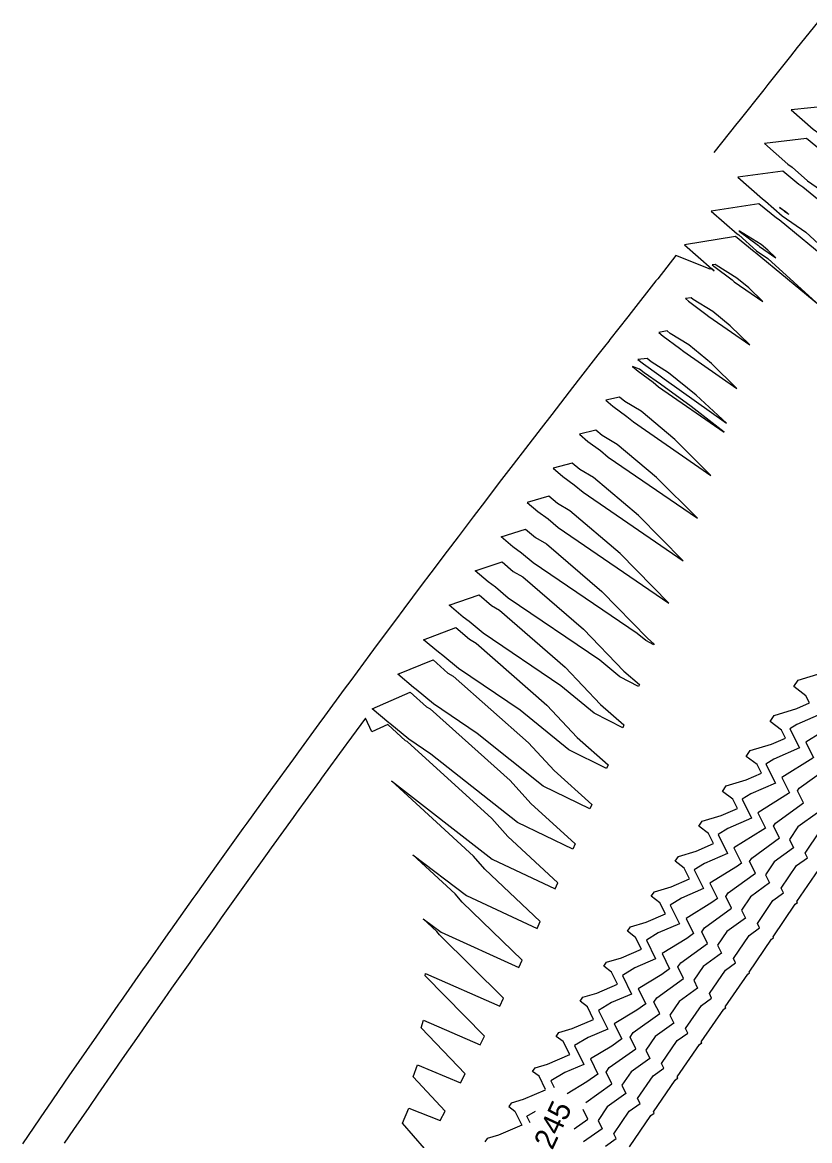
# Model space of a CAD drawing. Extents: x 1160447 to 1162032, y 616022 to 618272.
# Drawn here: x 1160785.4 to 1160877.4, y 616560 to 616690.7 of the extents above; entities that cross this region are included whole.
import ezdxf

# ---------------------------------------------------------------- set-up
doc = ezdxf.new("R2010")
doc.units = 0
doc.layers.add('D_Contours_Major', color=7, linetype='Continuous')
doc.layers.add('D_Contours_Minor', color=7, linetype='Continuous')

msp = doc.modelspace()

# ---------------------------------------------------------------- linework, layer by layer
at = {"layer": 'D_Contours_Major'}
for points in [[(1160880.5, 616608.73), (1160876.97, 616606.53), (1160877.88, 616604.7)], [(1160877.82, 616604.68), (1160874.17, 616602.41), (1160875.07, 616600.6), (1160874.97, 616600.52), (1160871.37, 616598.29), (1160872.27, 616596.49), (1160871.97, 616596.28), (1160868.58, 616594.17), (1160869.46, 616592.38), (1160868.99, 616592.04), (1160865.78, 616590.05), (1160866.66, 616588.28), (1160866.02, 616587.81), (1160862.99, 616585.92), (1160863.86, 616584.17), (1160863.07, 616583.59), (1160860.19, 616581.82), (1160861.06, 616580.06), (1160860.14, 616579.39), (1160857.4, 616577.72), (1160858.27, 616575.95), (1160857.22, 616575.2), (1160854.6, 616573.62), (1160855.47, 616571.84), (1160854.31, 616571.02), (1160851.81, 616569.51), (1160852.67, 616567.73), (1160851.41, 616566.83), (1160849.1, 616565.43)]]:
    msp.add_lwpolyline(points, dxfattribs=at)
at = {"layer": 'D_Contours_Minor'}
for points in [[(1160878.35, 616690.68), (1160875.99, 616687.73), (1160875.2, 616686.75), (1160872.55, 616683.42), (1160872.06, 616682.81), (1160869.14, 616679.14), (1160868.93, 616678.87), (1160866.22, 616675.46)], [(1160878.81, 616675.68), (1160877.06, 616677.1), (1160872.16, 616676.52), (1160874.89, 616674.12), (1160875.39, 616673.75), (1160877.18, 616672.17), (1160881.33, 616669.26)], [(1160888, 616662.09), (1160876.65, 616671.43), (1160876.16, 616671.74), (1160874.28, 616673.28), (1160869.04, 616672.57), (1160871.93, 616670.04), (1160872.26, 616669.79), (1160874.21, 616668.08), (1160876.98, 616666.14), (1160886.33, 616657.54)], [(1160885.94, 616657.63), (1160873.86, 616667.6), (1160873.54, 616667.8), (1160871.51, 616669.47), (1160865.91, 616668.63), (1160868.97, 616665.96), (1160869.14, 616665.83), (1160871.24, 616663.99), (1160872.53, 616663.09), (1160878.61, 616657.53), (1160871.08, 616663.77), (1160870.94, 616663.86), (1160868.75, 616665.66), (1160862.79, 616664.68), (1160866.01, 616661.88), (1160866.01, 616661.87), (1160866.27, 616661.65), (1160866, 616661.87), (1160865.81, 616661.83), (1160861.81, 616663.43), (1160859.68, 616660.72), (1160859.46, 616660.45), (1160856.57, 616656.77), (1160856.17, 616656.25), (1160854.09, 616653.6), (1160853.95, 616653.42), (1160853.47, 616652.81), (1160852.69, 616651.8), (1160850.37, 616648.84), (1160849.35, 616647.51), (1160847.29, 616644.86), (1160846.05, 616643.25), (1160844.22, 616640.87), (1160842.78, 616639), (1160841.16, 616636.88), (1160839.55, 616634.76), (1160838.11, 616632.87), (1160836.35, 616630.54), (1160835.07, 616628.86), (1160833.17, 616626.34), (1160832.05, 616624.84), (1160830.03, 616622.14), (1160829.04, 616620.81), (1160826.91, 616617.95), (1160826.04, 616616.77), (1160823.81, 616613.76), (1160823.05, 616612.72), (1160820.74, 616609.58), (1160820.07, 616608.67), (1160817.69, 616605.41), (1160817.1, 616604.6), (1160814.67, 616601.24), (1160814.15, 616600.53), (1160811.66, 616597.07), (1160811.21, 616596.45), (1160808.67, 616592.91), (1160808.28, 616592.36), (1160805.71, 616588.74), (1160805.36, 616588.26), (1160802.76, 616584.58), (1160802.45, 616584.15), (1160799.83, 616580.41), (1160799.56, 616580.03), (1160796.91, 616576.24), (1160796.68, 616575.91), (1160794.02, 616572.07), (1160793.81, 616571.78), (1160791.14, 616567.91), (1160790.95, 616567.63), (1160788.28, 616563.74), (1160788.11, 616563.48), (1160785.44, 616559.57)], [(1160846.57, 616565.93), (1160845.82, 616567.48), (1160845.05, 616568.05), (1160845.34, 616568.47), (1160846.81, 616568.9), (1160849.39, 616570.01), (1160848.64, 616571.55), (1160847.83, 616572.15), (1160848.13, 616572.6), (1160849.68, 616573.05), (1160852.18, 616574.12), (1160851.46, 616575.61), (1160850.6, 616576.25), (1160850.92, 616576.71), (1160852.56, 616577.2), (1160854.98, 616578.24), (1160854.28, 616579.67), (1160853.38, 616580.34), (1160853.71, 616580.82), (1160855.44, 616581.34), (1160857.78, 616582.35), (1160857.1, 616583.72), (1160856.16, 616584.43), (1160856.5, 616584.94), (1160858.34, 616585.48), (1160860.58, 616586.46), (1160859.93, 616587.77), (1160858.93, 616588.52), (1160859.29, 616589.05), (1160861.24, 616589.64), (1160863.39, 616590.57), (1160862.77, 616591.82), (1160861.71, 616592.61), (1160862.09, 616593.18), (1160864.16, 616593.8), (1160866.19, 616594.68), (1160865.61, 616595.86), (1160864.48, 616596.7), (1160864.89, 616597.3), (1160867.09, 616597.96), (1160869, 616598.79), (1160868.45, 616599.89), (1160867.26, 616600.79), (1160867.69, 616601.42), (1160870.03, 616602.13), (1160871.81, 616602.9), (1160871.3, 616603.93), (1160870.03, 616604.88), (1160870.48, 616605.55), (1160872.98, 616606.3), (1160874.61, 616607.01), (1160874.15, 616607.95), (1160872.81, 616608.97), (1160873.28, 616609.67), (1160875.93, 616610.47), (1160877.42, 616611.12), (1160877, 616611.97), (1160875.58, 616613.05), (1160876.09, 616613.8), (1160878.9, 616614.64)], [(1160832.43, 616559.04), (1160829.86, 616562), (1160830.6, 616563.74), (1160834.24, 616562.3), (1160834.83, 616563.39), (1160831.11, 616567.42), (1160831.62, 616568.8), (1160836.62, 616566.72), (1160837.17, 616567.76), (1160832.02, 616573.13), (1160832.3, 616574.04), (1160838.94, 616571.17), (1160839.45, 616572.17), (1160832.49, 616579.22), (1160832.55, 616579.51), (1160841.21, 616575.67), (1160841.67, 616576.61), (1160834.17, 616584.02), (1160833.85, 616584.39), (1160832.26, 616585.9), (1160834.37, 616584.32), (1160843.43, 616580.2), (1160843.84, 616581.07), (1160836.82, 616587.84), (1160835.99, 616588.8), (1160831.08, 616593.38), (1160837.35, 616588.6), (1160845.59, 616584.77), (1160845.95, 616585.57), (1160839.49, 616591.68), (1160838.14, 616593.21), (1160828.57, 616602), (1160840.32, 616592.88), (1160847.7, 616589.39), (1160848.01, 616590.1), (1160842.17, 616595.52), (1160840.28, 616597.62), (1160830.39, 616606.6), (1160830.2, 616606.7), (1160828.13, 616608.6), (1160826.29, 616607.75), (1160825.53, 616609.34), (1160823.35, 616606.38), (1160823.24, 616606.23), (1160820.39, 616602.32), (1160820.15, 616601.98), (1160817.44, 616598.25), (1160817.07, 616597.75), (1160814.5, 616594.17), (1160814.03, 616593.51), (1160811.57, 616590.08), (1160811, 616589.28), (1160808.65, 616585.99), (1160807.99, 616585.04), (1160805.75, 616581.88), (1160804.99, 616580.79), (1160802.86, 616577.77), (1160802, 616576.54), (1160799.98, 616573.65), (1160799.04, 616572.29), (1160797.11, 616569.52), (1160796.1, 616568.05), (1160794.26, 616565.38), (1160793.2, 616563.84), (1160791.42, 616561.24), (1160790.33, 616559.65)], [(1160879.05, 616609.96), (1160875.93, 616608.6), (1160875.13, 616608.1), (1160876.25, 616605.86), (1160873.25, 616604.55), (1160872.33, 616603.98), (1160873.44, 616601.75), (1160870.55, 616600.49), (1160869.53, 616599.86), (1160870.63, 616597.64), (1160867.86, 616596.43), (1160866.73, 616595.73), (1160867.83, 616593.53), (1160865.16, 616592.37), (1160863.94, 616591.61), (1160865.03, 616589.43), (1160862.45, 616588.3), (1160861.14, 616587.49), (1160862.22, 616585.32), (1160859.74, 616584.24), (1160858.35, 616583.38), (1160859.42, 616581.21), (1160857.02, 616580.17), (1160855.55, 616579.27), (1160856.62, 616577.09), (1160854.29, 616576.09), (1160852.76, 616575.16), (1160853.83, 616572.98), (1160851.57, 616572.02), (1160849.97, 616571.06), (1160851.03, 616568.87), (1160848.84, 616567.93), (1160847.18, 616566.93), (1160847.56, 616566.15)], [(1160851.27, 616564.42), (1160854.32, 616566.59), (1160853.65, 616567.97), (1160854.01, 616568.5), (1160857.11, 616570.7), (1160856.44, 616572.07), (1160856.8, 616572.59), (1160859.91, 616574.81), (1160859.24, 616576.16), (1160859.59, 616576.67), (1160862.7, 616578.92), (1160862.04, 616580.26), (1160862.38, 616580.75), (1160865.5, 616583.02), (1160864.83, 616584.36), (1160865.15, 616584.83), (1160868.3, 616587.13), (1160867.63, 616588.48), (1160867.92, 616588.91), (1160871.1, 616591.23), (1160870.42, 616592.6), (1160870.69, 616592.99), (1160873.9, 616595.34), (1160873.21, 616596.72), (1160873.45, 616597.07), (1160876.71, 616599.44), (1160876.01, 616600.83), (1160876.22, 616601.15), (1160879.51, 616603.54)], [(1160878.34, 616598.29), (1160876.06, 616596.63), (1160875.06, 616595.15), (1160875.54, 616594.19), (1160873.29, 616592.55), (1160872.26, 616591.03), (1160872.74, 616590.08), (1160870.53, 616588.47), (1160869.47, 616586.91), (1160869.94, 616585.98), (1160867.76, 616584.39), (1160866.68, 616582.8), (1160867.14, 616581.88), (1160864.99, 616580.31), (1160863.88, 616578.7), (1160864.34, 616577.77), (1160862.19, 616576.22), (1160861.08, 616574.61), (1160861.55, 616573.67), (1160859.38, 616572.12), (1160858.29, 616570.52), (1160858.76, 616569.56), (1160856.58, 616568.01), (1160855.49, 616566.43), (1160855.96, 616565.45), (1160853.78, 616563.9), (1160852.71, 616562.3), (1160853.17, 616561.34), (1160851.02, 616559.81)], [(1160853.58, 616559.32), (1160854.82, 616560.21), (1160854.55, 616560.76), (1160856.33, 616563.4), (1160857.61, 616564.31), (1160857.33, 616564.89), (1160859.14, 616567.53), (1160860.4, 616568.42), (1160860.13, 616568.97), (1160861.97, 616571.65), (1160863.19, 616572.52), (1160862.93, 616573.06), (1160864.79, 616575.77), (1160865.98, 616576.63), (1160865.73, 616577.14), (1160867.6, 616579.87), (1160868.78, 616580.73), (1160868.53, 616581.23), (1160870.37, 616583.95), (1160871.58, 616584.83), (1160871.32, 616585.35), (1160873.13, 616588.03), (1160874.37, 616588.93), (1160874.11, 616589.46), (1160875.9, 616592.11), (1160877.17, 616593.03), (1160876.9, 616593.58), (1160878.67, 616596.18)], [(1160856.39, 616559.22), (1160858.88, 616562.91), (1160859.25, 616563.18), (1160859.17, 616563.34), (1160861.71, 616567.04), (1160862.04, 616567.28), (1160861.97, 616567.42), (1160864.55, 616571.18), (1160864.83, 616571.38), (1160864.77, 616571.5), (1160867.39, 616575.31), (1160867.62, 616575.48), (1160867.57, 616575.58), (1160870.21, 616579.43), (1160870.42, 616579.58), (1160870.37, 616579.67), (1160872.98, 616583.51), (1160873.21, 616583.68), (1160873.16, 616583.78), (1160875.74, 616587.59), (1160876.01, 616587.78), (1160875.95, 616587.9), (1160878.51, 616591.66)], [(1160846.54, 616565.87), (1160843.94, 616564.76), (1160842.54, 616564.34), (1160842.27, 616563.94), (1160843, 616563.4), (1160843.8, 616561.77), (1160841.09, 616560.61), (1160839.75, 616560.21), (1160839.49, 616559.83)], [(1160844.76, 616562.04), (1160844.39, 616562.8), (1160845.4, 616563.41)], [(1160849.92, 616561.33), (1160851.53, 616562.48), (1160850.98, 616563.6)]]:
    msp.add_lwpolyline(points, dxfattribs=at)
for points in [[(1160881.47, 616679.63), (1160879.86, 616680.93), (1160875.29, 616680.45), (1160877.86, 616678.19), (1160878.51, 616677.72), (1160880.16, 616676.26), (1160885.57, 616672.44), (1160892.49, 616666), (1160905, 616658.76), (1160905.4, 616660.07), (1160894.52, 616668.78), (1160892.21, 616670.99), (1160882.26, 616679.12)], [(1160874.55, 616668.55), (1160874.52, 616668.58), (1160873.89, 616669.05), (1160874.59, 616668.61), (1160874.78, 616668.46), (1160875, 616668.24)], [(1160869.22, 616666.27), (1160869.2, 616666.29), (1160869.15, 616666.28), (1160869.18, 616666.26), (1160871.45, 616664.59), (1160871.59, 616664.47), (1160873.47, 616663.15), (1160872.54, 616664.06), (1160871.76, 616664.7)], [(1160866.51, 616662.29), (1160866.38, 616662.39), (1160866.04, 616662.34), (1160866.22, 616662.17), (1160868.38, 616660.59), (1160868.63, 616660.37), (1160871.95, 616658.06), (1160870.32, 616659.64), (1160868.93, 616660.79)], [(1160863.81, 616658.3), (1160863.57, 616658.5), (1160862.93, 616658.39), (1160863.27, 616658.08), (1160865.31, 616656.59), (1160865.67, 616656.28), (1160870.44, 616652.97), (1160868.13, 616655.22), (1160866.11, 616656.9)], [(1160861.14, 616654.32), (1160860.78, 616654.62), (1160859.82, 616654.43), (1160860.33, 616654), (1160862.24, 616652.61), (1160862.73, 616652.2), (1160868.93, 616647.88), (1160865.96, 616650.79), (1160863.31, 616653)], [(1160858.92, 616651), (1160858.45, 616651.38), (1160857.34, 616651.27), (1160858.01, 616650.77), (1160859.82, 616649.46), (1160860.43, 616649), (1160867.73, 616643.81), (1160864.18, 616647.1), (1160860.95, 616649.73)], [(1160858.08, 616649.73), (1160857.55, 616650.13), (1160856.72, 616650.47), (1160857.38, 616649.9), (1160859.16, 616648.61), (1160859.77, 616648.08), (1160867.43, 616642.79), (1160863.57, 616645.76), (1160860, 616648.4)], [(1160855.83, 616646.37), (1160855.22, 616646.88), (1160853.63, 616646.51), (1160854.45, 616645.8), (1160856.08, 616644.62), (1160856.83, 616643.97), (1160865.9, 616637.73), (1160861.68, 616641.91), (1160857.73, 616645.23)], [(1160853.2, 616642.39), (1160852.46, 616643.01), (1160850.55, 616642.54), (1160851.52, 616641.7), (1160853, 616640.62), (1160853.89, 616639.86), (1160864.31, 616632.71), (1160859.55, 616637.47), (1160854.95, 616641.35)], [(1160850.58, 616638.41), (1160849.7, 616639.16), (1160847.48, 616638.55), (1160848.59, 616637.6), (1160849.93, 616636.63), (1160850.96, 616635.75), (1160862.67, 616627.73), (1160857.42, 616633.03), (1160852.18, 616637.47)], [(1160847.97, 616634.44), (1160846.96, 616635.3), (1160844.42, 616634.56), (1160845.67, 616633.49), (1160846.86, 616632.64), (1160848.03, 616631.63), (1160860.99, 616622.8), (1160855.28, 616628.6), (1160849.42, 616633.59)], [(1160844.23, 616631.45), (1160845.38, 616630.47), (1160846.67, 616629.72), (1160853.14, 616624.16), (1160858.47, 616618.7), (1160859.28, 616618), (1160859.24, 616617.9), (1160858.27, 616618.41), (1160857.29, 616619.23), (1160845.11, 616627.51), (1160843.78, 616628.65), (1160842.76, 616629.38), (1160841.37, 616630.56)], [(1160841.51, 616627.61), (1160842.8, 616626.49), (1160843.93, 616625.85), (1160851, 616619.73), (1160855.73, 616614.83), (1160857.53, 616613.27), (1160857.45, 616613.05), (1160855.27, 616614.16), (1160852.9, 616616.13), (1160842.2, 616623.39), (1160840.71, 616624.65), (1160839.85, 616625.27), (1160838.34, 616626.55)], [(1160838.8, 616623.78), (1160840.24, 616622.53), (1160841.2, 616621.98), (1160848.86, 616615.31), (1160853.01, 616610.96), (1160855.73, 616608.57), (1160855.61, 616608.23), (1160852.27, 616609.92), (1160848.37, 616613.13), (1160839.28, 616619.27), (1160837.63, 616620.66), (1160836.95, 616621.16), (1160835.32, 616622.54)], [(1160836.1, 616619.96), (1160837.69, 616618.56), (1160838.48, 616618.12), (1160846.72, 616610.88), (1160850.28, 616607.1), (1160853.88, 616603.9), (1160853.71, 616603.46), (1160849.28, 616605.66), (1160843.62, 616610.26), (1160836.38, 616615.14), (1160834.55, 616616.68), (1160834.05, 616617.04), (1160832.31, 616618.51)], [(1160833.43, 616616.16), (1160835.17, 616614.6), (1160835.77, 616614.27), (1160844.57, 616606.46), (1160847.57, 616603.23), (1160851.98, 616599.27), (1160851.76, 616598.73), (1160846.29, 616601.41), (1160838.59, 616607.57), (1160833.48, 616611.01), (1160831.47, 616612.69), (1160831.15, 616612.92), (1160829.31, 616614.47)], [(1160830.77, 616612.37), (1160832.67, 616610.65), (1160833.07, 616610.43), (1160842.43, 616602.04), (1160844.87, 616599.38), (1160850.02, 616594.67), (1160849.76, 616594.04), (1160843.3, 616597.14), (1160833.18, 616605.13), (1160830.58, 616606.87), (1160828.38, 616608.72), (1160828.27, 616608.8), (1160826.32, 616610.43)]]:
    msp.add_lwpolyline(points, close=True, dxfattribs=at)

# ---------------------------------------------------------------- texts
at = {"layer": 'D_Contours_Major'}
msp.add_text('245', height=2.49, rotation=65.0096, dxfattribs=at).set_placement((1160847.36, 616558.78))

doc.saveas('drawing.dxf')
